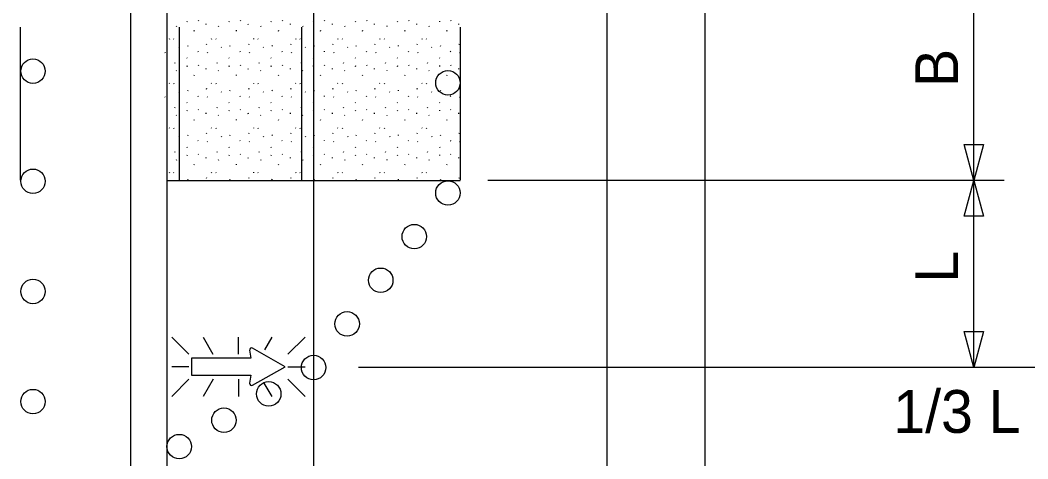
# Model space of a CAD drawing. Extents: x 16735 to 18475, y 6983 to 8262.
# Drawn here: x 17017.1 to 17181.9, y 7667.2 to 7738.8 of the extents above; entities that cross this region are included whole.
import ezdxf

# ---------------------------------------------------------------- set-up
doc = ezdxf.new("R2010")
doc.units = 0
for name, color, linetype in [('ALI_LEGAL_EX', 7, 'Continuous'), ('MT_SCRATCH_LEVEL_A', 7, 'Continuous'), ('PAVT_EDGE_EX', 7, 'Continuous'), ('TRAFFIC_SIGNS_PR', 7, 'Continuous'), ('TYPICAL_TEXT_DIMEN_PR', 7, 'Continuous')]:
    doc.layers.add(name, color=color, linetype=linetype)

msp = doc.modelspace()

# ---------------------------------------------------------------- linework, layer by layer
at = {"layer": 'ALI_LEGAL_EX'}
for points in [[(17017.08, 7737.7), (17017.08, 7712.7)], [(17043.08, 7737.7), (17043.08, 7712.7)], [(17063.08, 7737.7), (17063.08, 7712.7)], [(17089.08, 7737.7), (17089.08, 7712.7)]]:
    msp.add_lwpolyline(points, dxfattribs=at)
at = {"layer": 'MT_SCRATCH_LEVEL_A'}
for p, q in [((17044.38, 7738.56), (17044.43, 7738.68)), ((17046.18, 7738.82), (17046.23, 7738.74)), ((17047.46, 7738.24), (17047.47, 7738.12)), ((17051.27, 7738.56), (17051.32, 7738.68)), ((17053.06, 7738.82), (17053.12, 7738.74)), ((17054.35, 7738.24), (17054.36, 7738.12)), ((17058.15, 7738.56), (17058.21, 7738.68)), ((17059.95, 7738.82), (17060, 7738.74)), ((17061.23, 7738.24), (17061.25, 7738.12)), ((17065.04, 7738.56), (17065.1, 7738.68)), ((17066.84, 7738.82), (17066.89, 7738.74)), ((17068.12, 7738.24), (17068.13, 7738.12)), ((17071.93, 7738.56), (17071.98, 7738.68)), ((17073.73, 7738.82), (17073.78, 7738.74)), ((17075.01, 7738.24), (17075.02, 7738.12)), ((17078.82, 7738.56), (17078.87, 7738.68)), ((17080.61, 7738.82), (17080.67, 7738.74)), ((17081.9, 7738.24), (17081.91, 7738.12)), ((17085.71, 7738.56), (17085.76, 7738.68)), ((17087.5, 7738.82), (17087.55, 7738.74)), ((17088.78, 7738.24), (17088.8, 7738.12)), ((17042.6, 7737.9), (17042.65, 7737.82)), ((17045.56, 7737.06), (17045.61, 7737.18)), ((17049.49, 7737.9), (17049.54, 7737.82)), ((17052.45, 7737.06), (17052.5, 7737.18)), ((17056.38, 7737.9), (17056.43, 7737.82)), ((17059.33, 7737.06), (17059.39, 7737.18)), ((17063.26, 7737.9), (17063.31, 7737.82)), ((17066.22, 7737.06), (17066.27, 7737.18)), ((17070.15, 7737.9), (17070.2, 7737.82)), ((17073.11, 7737.06), (17073.16, 7737.18)), ((17077.04, 7737.9), (17077.09, 7737.82)), ((17080, 7737.06), (17080.05, 7737.18)), ((17083.93, 7737.9), (17083.98, 7737.82)), ((17086.88, 7737.06), (17086.94, 7737.18)), ((17041.46, 7735.83), (17041.51, 7735.75)), ((17042.19, 7735.8), (17042.24, 7735.72)), ((17047.58, 7734.87), (17047.63, 7734.98)), ((17048.34, 7735.83), (17048.39, 7735.75)), ((17049.08, 7735.8), (17049.13, 7735.72)), ((17054.47, 7734.87), (17054.52, 7734.98)), ((17055.23, 7735.83), (17055.28, 7735.75)), ((17055.97, 7735.8), (17056.02, 7735.72)), ((17061.35, 7734.87), (17061.4, 7734.98)), ((17062.12, 7735.83), (17062.17, 7735.75)), ((17062.85, 7735.8), (17062.91, 7735.72)), ((17068.24, 7734.87), (17068.29, 7734.98)), ((17069.01, 7735.83), (17069.06, 7735.75)), ((17069.74, 7735.8), (17069.79, 7735.72)), ((17075.13, 7734.87), (17075.18, 7734.98)), ((17075.89, 7735.83), (17075.94, 7735.75)), ((17076.63, 7735.8), (17076.68, 7735.72)), ((17082.02, 7734.87), (17082.07, 7734.98)), ((17082.78, 7735.83), (17082.83, 7735.75)), ((17083.52, 7735.8), (17083.57, 7735.72)), ((17088.9, 7734.87), (17088.96, 7734.98)), ((17040.77, 7733.6), (17040.82, 7733.52)), ((17043.06, 7734.42), (17043.11, 7734.34)), ((17044.51, 7734.57), (17044.56, 7734.68)), ((17046.13, 7733.74), (17046.18, 7733.66)), ((17047.66, 7733.6), (17047.71, 7733.52)), ((17049.95, 7734.42), (17050, 7734.34)), ((17051.4, 7734.57), (17051.45, 7734.68)), ((17053.02, 7733.74), (17053.07, 7733.66)), ((17054.55, 7733.6), (17054.6, 7733.52)), ((17056.84, 7734.42), (17056.89, 7734.34)), ((17058.28, 7734.57), (17058.34, 7734.68)), ((17059.9, 7733.74), (17059.96, 7733.66)), ((17061.43, 7733.6), (17061.49, 7733.52)), ((17063.72, 7734.42), (17063.78, 7734.34)), ((17065.17, 7734.57), (17065.22, 7734.68)), ((17066.79, 7733.74), (17066.84, 7733.66)), ((17068.32, 7733.6), (17068.37, 7733.52)), ((17070.61, 7734.42), (17070.66, 7734.34)), ((17072.06, 7734.57), (17072.11, 7734.68)), ((17073.68, 7733.74), (17073.73, 7733.66)), ((17075.21, 7733.6), (17075.26, 7733.52)), ((17077.5, 7734.42), (17077.55, 7734.34)), ((17078.95, 7734.57), (17079, 7734.68)), ((17080.57, 7733.74), (17080.62, 7733.66)), ((17082.1, 7733.6), (17082.15, 7733.52)), ((17084.39, 7734.42), (17084.44, 7734.34)), ((17085.83, 7734.57), (17085.89, 7734.68)), ((17087.45, 7733.74), (17087.51, 7733.66)), ((17088.98, 7733.6), (17089.03, 7733.52)), ((17042.41, 7731.81), (17042.46, 7731.93)), ((17044.34, 7732.68), (17044.39, 7732.6)), ((17046.18, 7731.53), (17046.23, 7731.45)), ((17049.3, 7731.81), (17049.35, 7731.93)), ((17051.22, 7732.68), (17051.28, 7732.6)), ((17053.06, 7731.53), (17053.12, 7731.45)), ((17056.19, 7731.81), (17056.24, 7731.93)), ((17058.11, 7732.68), (17058.16, 7732.6)), ((17059.95, 7731.53), (17060, 7731.45)), ((17063.08, 7731.81), (17063.13, 7731.93)), ((17065, 7732.68), (17065.05, 7732.6)), ((17066.84, 7731.53), (17066.89, 7731.45)), ((17069.96, 7731.81), (17070.01, 7731.93)), ((17071.89, 7732.68), (17071.94, 7732.6)), ((17073.73, 7731.53), (17073.78, 7731.45)), ((17076.85, 7731.81), (17076.9, 7731.93)), ((17078.78, 7732.68), (17078.83, 7732.6)), ((17080.61, 7731.53), (17080.67, 7731.45)), ((17083.74, 7731.81), (17083.79, 7731.93)), ((17085.66, 7732.68), (17085.72, 7732.6)), ((17087.5, 7731.53), (17087.55, 7731.45)), ((17042.6, 7730.61), (17042.65, 7730.53)), ((17044.38, 7731.28), (17044.43, 7731.4)), ((17045.56, 7729.78), (17045.61, 7729.89)), ((17047.46, 7730.95), (17047.47, 7730.84)), ((17049.49, 7730.61), (17049.54, 7730.53)), ((17051.27, 7731.28), (17051.32, 7731.4)), ((17052.45, 7729.78), (17052.5, 7729.89)), ((17054.35, 7730.95), (17054.36, 7730.84)), ((17056.38, 7730.61), (17056.43, 7730.53)), ((17058.15, 7731.28), (17058.21, 7731.4)), ((17059.33, 7729.78), (17059.39, 7729.89)), ((17061.23, 7730.95), (17061.25, 7730.84)), ((17063.26, 7730.61), (17063.31, 7730.53)), ((17065.04, 7731.28), (17065.1, 7731.4)), ((17066.22, 7729.78), (17066.27, 7729.89)), ((17068.12, 7730.95), (17068.13, 7730.84)), ((17070.15, 7730.61), (17070.2, 7730.53)), ((17071.93, 7731.28), (17071.98, 7731.4)), ((17073.11, 7729.78), (17073.16, 7729.89)), ((17075.01, 7730.95), (17075.02, 7730.84)), ((17077.04, 7730.61), (17077.09, 7730.53)), ((17078.82, 7731.28), (17078.87, 7731.4)), ((17080, 7729.78), (17080.05, 7729.89)), ((17081.9, 7730.95), (17081.91, 7730.84)), ((17083.93, 7730.61), (17083.98, 7730.53)), ((17085.71, 7731.28), (17085.76, 7731.4)), ((17086.88, 7729.78), (17086.94, 7729.89)), ((17088.78, 7730.95), (17088.8, 7730.84)), ((17041.46, 7728.54), (17041.51, 7728.46)), ((17042.19, 7728.51), (17042.24, 7728.43)), ((17048.34, 7728.54), (17048.39, 7728.46)), ((17049.08, 7728.51), (17049.13, 7728.43)), ((17055.23, 7728.54), (17055.28, 7728.46)), ((17055.97, 7728.51), (17056.02, 7728.43)), ((17062.12, 7728.54), (17062.17, 7728.46)), ((17062.85, 7728.51), (17062.91, 7728.43)), ((17069.01, 7728.54), (17069.06, 7728.46)), ((17069.74, 7728.51), (17069.79, 7728.43)), ((17075.89, 7728.54), (17075.94, 7728.46)), ((17076.63, 7728.51), (17076.68, 7728.43)), ((17082.78, 7728.54), (17082.83, 7728.46)), ((17083.52, 7728.51), (17083.57, 7728.43)), ((17043.06, 7727.13), (17043.11, 7727.05)), ((17044.51, 7727.28), (17044.56, 7727.4)), ((17047.58, 7727.58), (17047.63, 7727.7)), ((17049.95, 7727.13), (17050, 7727.05)), ((17051.4, 7727.28), (17051.45, 7727.4)), ((17054.47, 7727.58), (17054.52, 7727.7)), ((17056.84, 7727.13), (17056.89, 7727.05)), ((17058.28, 7727.28), (17058.34, 7727.4)), ((17061.35, 7727.58), (17061.4, 7727.7)), ((17063.72, 7727.13), (17063.78, 7727.05)), ((17065.17, 7727.28), (17065.22, 7727.4)), ((17068.24, 7727.58), (17068.29, 7727.7)), ((17070.61, 7727.13), (17070.66, 7727.05)), ((17072.06, 7727.28), (17072.11, 7727.4)), ((17075.13, 7727.58), (17075.18, 7727.7)), ((17077.5, 7727.13), (17077.55, 7727.05)), ((17078.95, 7727.28), (17079, 7727.4)), ((17082.02, 7727.58), (17082.07, 7727.7)), ((17084.39, 7727.13), (17084.44, 7727.05)), ((17085.83, 7727.28), (17085.89, 7727.4)), ((17088.9, 7727.58), (17088.96, 7727.7)), ((17040.77, 7726.31), (17040.82, 7726.24)), ((17044.34, 7725.4), (17044.39, 7725.32)), ((17046.13, 7726.45), (17046.18, 7726.38)), ((17047.66, 7726.31), (17047.71, 7726.24)), ((17051.22, 7725.4), (17051.28, 7725.32)), ((17053.02, 7726.45), (17053.07, 7726.38)), ((17054.55, 7726.31), (17054.6, 7726.24)), ((17058.11, 7725.4), (17058.16, 7725.32)), ((17059.9, 7726.45), (17059.96, 7726.38)), ((17061.43, 7726.31), (17061.49, 7726.24)), ((17065, 7725.4), (17065.05, 7725.32)), ((17066.79, 7726.45), (17066.84, 7726.38)), ((17068.32, 7726.31), (17068.37, 7726.24)), ((17071.89, 7725.4), (17071.94, 7725.32)), ((17073.68, 7726.45), (17073.73, 7726.38)), ((17075.21, 7726.31), (17075.26, 7726.24)), ((17078.78, 7725.4), (17078.83, 7725.32)), ((17080.57, 7726.45), (17080.62, 7726.38)), ((17082.1, 7726.31), (17082.15, 7726.24)), ((17085.66, 7725.4), (17085.72, 7725.32)), ((17087.45, 7726.45), (17087.51, 7726.38)), ((17088.98, 7726.31), (17089.03, 7726.24)), ((17042.41, 7724.53), (17042.46, 7724.64)), ((17042.6, 7723.33), (17042.65, 7723.25)), ((17044.38, 7723.99), (17044.43, 7724.11)), ((17046.18, 7724.25), (17046.23, 7724.17)), ((17047.46, 7723.67), (17047.47, 7723.55)), ((17049.3, 7724.53), (17049.35, 7724.64)), ((17049.49, 7723.33), (17049.54, 7723.25)), ((17051.27, 7723.99), (17051.32, 7724.11)), ((17053.06, 7724.25), (17053.12, 7724.17)), ((17054.35, 7723.67), (17054.36, 7723.55)), ((17056.19, 7724.53), (17056.24, 7724.64)), ((17056.38, 7723.33), (17056.43, 7723.25)), ((17058.15, 7723.99), (17058.21, 7724.11)), ((17059.95, 7724.25), (17060, 7724.17)), ((17061.23, 7723.67), (17061.25, 7723.55)), ((17063.08, 7724.53), (17063.13, 7724.64)), ((17063.26, 7723.33), (17063.31, 7723.25)), ((17065.04, 7723.99), (17065.1, 7724.11)), ((17066.84, 7724.25), (17066.89, 7724.17)), ((17068.12, 7723.67), (17068.13, 7723.55)), ((17069.96, 7724.53), (17070.01, 7724.64)), ((17070.15, 7723.33), (17070.2, 7723.25)), ((17071.93, 7723.99), (17071.98, 7724.11)), ((17073.73, 7724.25), (17073.78, 7724.17)), ((17075.01, 7723.67), (17075.02, 7723.55)), ((17076.85, 7724.53), (17076.9, 7724.64)), ((17077.04, 7723.33), (17077.09, 7723.25)), ((17078.82, 7723.99), (17078.87, 7724.11)), ((17080.61, 7724.25), (17080.67, 7724.17)), ((17081.9, 7723.67), (17081.91, 7723.55)), ((17083.74, 7724.53), (17083.79, 7724.64)), ((17083.93, 7723.33), (17083.98, 7723.25)), ((17085.71, 7723.99), (17085.76, 7724.11)), ((17087.5, 7724.25), (17087.55, 7724.17)), ((17088.78, 7723.67), (17088.8, 7723.55)), ((17045.56, 7722.49), (17045.61, 7722.61)), ((17052.45, 7722.49), (17052.5, 7722.61)), ((17059.33, 7722.49), (17059.39, 7722.61)), ((17066.22, 7722.49), (17066.27, 7722.61)), ((17073.11, 7722.49), (17073.16, 7722.61)), ((17080, 7722.49), (17080.05, 7722.61)), ((17086.88, 7722.49), (17086.94, 7722.61)), ((17041.46, 7721.26), (17041.51, 7721.18)), ((17042.19, 7721.23), (17042.24, 7721.15)), ((17044.51, 7720), (17044.56, 7720.12)), ((17047.58, 7720.3), (17047.63, 7720.41)), ((17048.34, 7721.26), (17048.39, 7721.18)), ((17049.08, 7721.23), (17049.13, 7721.15)), ((17051.4, 7720), (17051.45, 7720.12)), ((17054.47, 7720.3), (17054.52, 7720.41)), ((17055.23, 7721.26), (17055.28, 7721.18)), ((17055.97, 7721.23), (17056.02, 7721.15)), ((17058.28, 7720), (17058.34, 7720.12)), ((17061.35, 7720.3), (17061.4, 7720.41)), ((17062.12, 7721.26), (17062.17, 7721.18)), ((17062.85, 7721.23), (17062.91, 7721.15)), ((17065.17, 7720), (17065.22, 7720.12)), ((17068.24, 7720.3), (17068.29, 7720.41)), ((17069.01, 7721.26), (17069.06, 7721.18)), ((17069.74, 7721.23), (17069.79, 7721.15)), ((17072.06, 7720), (17072.11, 7720.12)), ((17075.13, 7720.3), (17075.18, 7720.41)), ((17075.89, 7721.26), (17075.94, 7721.18)), ((17076.63, 7721.23), (17076.68, 7721.15)), ((17078.95, 7720), (17079, 7720.12)), ((17082.02, 7720.3), (17082.07, 7720.41)), ((17082.78, 7721.26), (17082.83, 7721.18)), ((17083.52, 7721.23), (17083.57, 7721.15)), ((17085.83, 7720), (17085.89, 7720.12)), ((17088.9, 7720.3), (17088.96, 7720.41)), ((17043.06, 7719.85), (17043.11, 7719.77)), ((17046.13, 7719.17), (17046.18, 7719.09)), ((17047.66, 7719.03), (17047.71, 7718.95)), ((17049.95, 7719.85), (17050, 7719.77)), ((17053.02, 7719.17), (17053.07, 7719.09)), ((17054.55, 7719.03), (17054.6, 7718.95)), ((17056.84, 7719.85), (17056.89, 7719.77)), ((17059.9, 7719.17), (17059.96, 7719.09)), ((17061.43, 7719.03), (17061.49, 7718.95)), ((17063.72, 7719.85), (17063.78, 7719.77)), ((17066.79, 7719.17), (17066.84, 7719.09)), ((17068.32, 7719.03), (17068.37, 7718.95)), ((17070.61, 7719.85), (17070.66, 7719.77)), ((17073.68, 7719.17), (17073.73, 7719.09)), ((17075.21, 7719.03), (17075.26, 7718.95)), ((17077.5, 7719.85), (17077.55, 7719.77)), ((17080.57, 7719.17), (17080.62, 7719.09)), ((17082.1, 7719.03), (17082.15, 7718.95)), ((17084.39, 7719.85), (17084.44, 7719.77)), ((17087.45, 7719.17), (17087.51, 7719.09)), ((17088.98, 7719.03), (17089.03, 7718.95)), ((17042.41, 7717.24), (17042.46, 7717.36)), ((17044.34, 7718.11), (17044.39, 7718.03)), ((17044.38, 7716.71), (17044.43, 7716.83)), ((17046.18, 7716.96), (17046.23, 7716.88)), ((17049.3, 7717.24), (17049.35, 7717.36)), ((17051.22, 7718.11), (17051.28, 7718.03)), ((17051.27, 7716.71), (17051.32, 7716.83)), ((17053.06, 7716.96), (17053.12, 7716.88)), ((17056.19, 7717.24), (17056.24, 7717.36)), ((17058.11, 7718.11), (17058.16, 7718.03)), ((17058.15, 7716.71), (17058.21, 7716.83)), ((17059.95, 7716.96), (17060, 7716.88)), ((17063.08, 7717.24), (17063.13, 7717.36)), ((17065, 7718.11), (17065.05, 7718.03)), ((17065.04, 7716.71), (17065.1, 7716.83)), ((17066.84, 7716.96), (17066.89, 7716.88)), ((17069.96, 7717.24), (17070.01, 7717.36)), ((17071.89, 7718.11), (17071.94, 7718.03)), ((17071.93, 7716.71), (17071.98, 7716.83)), ((17073.73, 7716.96), (17073.78, 7716.88)), ((17076.85, 7717.24), (17076.9, 7717.36)), ((17078.78, 7718.11), (17078.83, 7718.03)), ((17078.82, 7716.71), (17078.87, 7716.83)), ((17080.61, 7716.96), (17080.67, 7716.88)), ((17083.74, 7717.24), (17083.79, 7717.36)), ((17085.66, 7718.11), (17085.72, 7718.03)), ((17085.71, 7716.71), (17085.76, 7716.83)), ((17087.5, 7716.96), (17087.55, 7716.88)), ((17042.6, 7716.04), (17042.65, 7715.96)), ((17045.56, 7715.21), (17045.61, 7715.32)), ((17047.46, 7716.38), (17047.47, 7716.27)), ((17049.49, 7716.04), (17049.54, 7715.96)), ((17052.45, 7715.21), (17052.5, 7715.32)), ((17054.35, 7716.38), (17054.36, 7716.27)), ((17056.38, 7716.04), (17056.43, 7715.96)), ((17059.33, 7715.21), (17059.39, 7715.32)), ((17061.23, 7716.38), (17061.25, 7716.27)), ((17063.26, 7716.04), (17063.31, 7715.96)), ((17066.22, 7715.21), (17066.27, 7715.32)), ((17068.12, 7716.38), (17068.13, 7716.27)), ((17070.15, 7716.04), (17070.2, 7715.96)), ((17073.11, 7715.21), (17073.16, 7715.32)), ((17075.01, 7716.38), (17075.02, 7716.27)), ((17077.04, 7716.04), (17077.09, 7715.96)), ((17080, 7715.21), (17080.05, 7715.32)), ((17081.9, 7716.38), (17081.91, 7716.27)), ((17083.93, 7716.04), (17083.98, 7715.96)), ((17086.88, 7715.21), (17086.94, 7715.32)), ((17088.78, 7716.38), (17088.8, 7716.27)), ((17041.46, 7713.97), (17041.51, 7713.89)), ((17042.19, 7713.94), (17042.24, 7713.86)), ((17048.34, 7713.97), (17048.39, 7713.89)), ((17049.08, 7713.94), (17049.13, 7713.86)), ((17055.23, 7713.97), (17055.28, 7713.89)), ((17055.97, 7713.94), (17056.02, 7713.86)), ((17062.12, 7713.97), (17062.17, 7713.89)), ((17062.85, 7713.94), (17062.91, 7713.86)), ((17069.01, 7713.97), (17069.06, 7713.89)), ((17069.74, 7713.94), (17069.79, 7713.86)), ((17075.89, 7713.97), (17075.94, 7713.89)), ((17076.63, 7713.94), (17076.68, 7713.86)), ((17082.78, 7713.97), (17082.83, 7713.89)), ((17083.52, 7713.94), (17083.57, 7713.86)), ((17041.08, 7712.65), (17089.08, 7712.65)), ((17044.51, 7712.71), (17044.56, 7712.83)), ((17047.58, 7713.01), (17047.63, 7713.13)), ((17051.4, 7712.71), (17051.45, 7712.83)), ((17054.47, 7713.01), (17054.52, 7713.13)), ((17058.28, 7712.71), (17058.34, 7712.83)), ((17061.35, 7713.01), (17061.4, 7713.13)), ((17065.17, 7712.71), (17065.22, 7712.83)), ((17068.24, 7713.01), (17068.29, 7713.13)), ((17072.06, 7712.71), (17072.11, 7712.83)), ((17075.13, 7713.01), (17075.18, 7713.13)), ((17078.95, 7712.71), (17079, 7712.83)), ((17082.02, 7713.01), (17082.07, 7713.13)), ((17085.83, 7712.71), (17085.89, 7712.83)), ((17088.9, 7713.01), (17088.96, 7713.13))]:
    msp.add_line(p, q, dxfattribs=at)
at = {"layer": 'PAVT_EDGE_EX'}
for p, q in [((17035.15, 8262.34), (17035.15, 7433.15)), ((17041.08, 8195.21), (17041.08, 7357.91)), ((17065.08, 8195.21), (17065.08, 7357.91)), ((17113.08, 8195.21), (17113.08, 7357.91)), ((17129.08, 8195.21), (17129.08, 7357.91))]:
    msp.add_line(p, q, dxfattribs=at)
at = {"layer": 'TRAFFIC_SIGNS_PR'}
for p, q in [((17044.7, 7684.23), (17041.88, 7687.05)), ((17047, 7687.05), (17048.62, 7684.23)), ((17052.78, 7684.23), (17052.78, 7687.05)), ((17058.25, 7687.05), (17057.05, 7684.95)), ((17063.69, 7687.04), (17060.87, 7684.23)), ((17044.7, 7682.19), (17041.88, 7682.19)), ((17060.87, 7682.19), (17063.69, 7682.19)), ((17044.7, 7680.16), (17041.88, 7677.34)), ((17048.65, 7680.16), (17047.02, 7677.34)), ((17052.78, 7680.16), (17052.78, 7677.34)), ((17056.97, 7679.53), (17058.23, 7677.34)), ((17063.69, 7677.34), (17060.87, 7680.16))]:
    msp.add_line(p, q, dxfattribs=at)
for points in [[(17054.61, 7684.88), (17054.84, 7683.58), (17045.12, 7683.58), (17045.12, 7680.84), (17054.84, 7680.84), (17054.61, 7679.53)], [(17055.11, 7679.18), (17060.42, 7682.19), (17055.11, 7685.23)]]:
    msp.add_lwpolyline(points, dxfattribs=at)
for centre in [(17019.18, 7730.5), (17087.06, 7728.59), (17019.18, 7712.5), (17087.06, 7710.59), (17081.56, 7703.46), (17076.07, 7696.33), (17019.18, 7694.5), (17070.57, 7689.2), (17065.08, 7682.07), (17057.75, 7677.76), (17019.18, 7676.5), (17050.42, 7673.46), (17043.1, 7669.15)]:
    msp.add_circle(centre, 2, dxfattribs=at)
for centre, start, end in [((17054.95, 7684.93), 61.4833, 189.9593), ((17054.95, 7679.48), 170.7308, 298.8916)]:
    msp.add_arc(centre, 0.341, start, end, dxfattribs=at)
at = {"layer": 'TYPICAL_TEXT_DIMEN_PR'}
for p, q in [((17173.08, 7712.65), (17173.08, 7744.71)), ((17173.08, 7712.65), (17171.51, 7718.51)), ((17171.51, 7718.51), (17173.08, 7718.51)), ((17173.08, 7718.51), (17174.65, 7718.51)), ((17174.65, 7718.51), (17173.08, 7712.65)), ((17178.08, 7712.65), (17093.58, 7712.65)), ((17171.51, 7706.78), (17173.08, 7712.65)), ((17173.08, 7712.65), (17174.65, 7706.78)), ((17173.08, 7682.07), (17173.08, 7712.65)), ((17173.08, 7706.78), (17171.51, 7706.78)), ((17174.65, 7706.78), (17173.08, 7706.78)), ((17173.08, 7682.07), (17171.51, 7687.93)), ((17171.51, 7687.93), (17173.08, 7687.93)), ((17173.08, 7687.93), (17174.65, 7687.93)), ((17174.65, 7687.93), (17173.08, 7682.07)), ((17213.45, 7682.07), (17072.44, 7682.07))]:
    msp.add_line(p, q, dxfattribs=at)

# ---------------------------------------------------------------- texts
for s, p in [('B', (17170.52, 7727.91)), ('L', (17170.52, 7695.94))]:
    msp.add_text(s, height=7, rotation=90, dxfattribs=at).set_placement(p)
msp.add_text('1/3 L', height=7, dxfattribs=at).set_placement((17159.92, 7671.39))

doc.saveas('drawing.dxf')
